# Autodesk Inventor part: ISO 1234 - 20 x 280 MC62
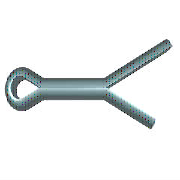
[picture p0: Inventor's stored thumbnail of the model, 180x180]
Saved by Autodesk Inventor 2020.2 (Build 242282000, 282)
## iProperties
Manager: www.cadconsulting.pl
Company: Fabian Stasiak CAD Consulting
IsCustomPart: 0
Created: 2010-10
Part Number: ISO 1234 - 20 x 280 MC62
Material: Mosiądz, jasnożółty
Description: Zawleczka
Document SubType Name: Modeling
Standard: ISO 1234
Designer: F.Stasiak
Standard Revision: Druga edycja 1997-11-01
Standards Organization: ISO
Language: pl-PL
Size Designation: 20 x 280
Categories: <MemberInstance><Categories><Category DisplayName="Mocowania" InternalName="e4da775c-781d-43d5-af7c-5136215cf5a6" Mnemonic="FSTN"><Category DisplayName="Kołki"
Density: 8.47 g/cm^3
Appearance: Metal-Mosiądz
Author: F.Stasiak
Subject: Zbiór ćwiczeń. Autodesk Inventor 2020. Kurs podstawowy
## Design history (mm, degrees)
sketch "Szkic1"
  geometry: L1 (0, 9.65)-(248, 9.65); L2 (0, -9.65)-(248, -9.65); L3 (248, 9.65)-(280, 21.91); L4 (280, 21.91)-(283.224, 13.495); L5 (283.224, 13.495)-(248, 0); L6 (248, 0)-(289.524, -15.909); L7 (289.524, -15.909)-(286.3, -24.323); L8 (286.3, -24.323)-(248, -9.65); L9 (0, 0)-(-16.309, -8.511); L10 (0, 0)-(-16.309, 8.511); L11 (0, 9.65)-(0, -9.65); L12 (0, 9.65)-(-10.457, 16.267); L13 (0, -9.65)-(-10.457, -16.267); L14 (-40, 0)-(248, 0); L15 (248, 9.65)-(248, -9.65); A1 r 19.25 centre (-20.75, 0) between (-10.457, 16.267) and (-10.457, -16.267); A2 r 9.6 centre (-20.75, 0) between (-16.309, 8.511) and (-16.309, -8.511); 1 further point
  constraints: 30 end point, 5 point on circle, 4 parallel, 4 perpendicular, 4 point on line, 4 tangent, 2 centre point, 2 midpoint, 1 coincident, 1 horizontal
  dimensions: "d0" = 248 distance of L1.start L1.end (= MSIAB); "d1" = 280 horizontal distance of L1.start L3.end (= SNLG); "d2" = 159.037 deg angle of L1 L3; "d3" = 159.037 deg angle of L2 L8; "d4" = 6.3 horizontal distance of L3.end L7.end (= LGDIF); "d5" = 9.6 radius of A2 (= -0.5 x SNND1 + 0.5 x KBR); "d6" = 19.25 radius of A1 (= 0.5 x KBR); "d7" = 9.65 distance from line of L1 L9.start (= 0.5 x SNND1); "d8" = 9.65 distance between parallel lines of L2 L14 (= 0.5 x SNND1); "d9" = 20.75 distance from line of L11 A1.centre (= KOL - 0.5 x KBR)
extrude "Bryła" new body sketch "Szkic1" stored distance "d10" = 19.3 (= SNND1); taper "d11" = 0 deg
workaxis "Work Axis1"
workplane "Work Plane1"
workplane "Work Plane3"
body "Solid1"
fillet "Zaokrąglenie" dims "d12" = 6.755 (= 0.35 x SNND1)
other parameters: "SNLG" = 280 [user parameter; used in 1 equation term], "SNND1" = 19.3 [user parameter; used in 5 equation terms], "KBR" = 38.5 [user parameter; used in 3 equation terms], "LGDIF" = 6.3 [user parameter; used in 1 equation term], "MSIAB" = 248 [user parameter; used in 1 equation term], "d15" = 0, "d16" = 0, "d17" = 0, "DSH" = 26 [user parameter]
